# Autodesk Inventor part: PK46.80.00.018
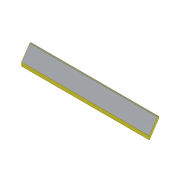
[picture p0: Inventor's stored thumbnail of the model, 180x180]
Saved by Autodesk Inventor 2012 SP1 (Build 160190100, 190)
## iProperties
Shininess: 64.0
Length Units: 11269
Angle Units: 11279
Time Units: 11290
Mass Units: 11283
Length Display Precision: 3
Angle Display Precision: 2
Compacted: True
Part Number: PK46.80.00.018
Document SubType Name: Modeling
Created: 2005-01
Material: Steel, Mild
Designer: SAlex
Manufacturer: Standard
Standards Organization: Custom
Density: 7.86 g/cm^3
Density: 0.0
Volumn: 0.0
Area: 0.0
PropertySet Name: Model Information
Control State: 0
Master: False
Checked Out: False
Checked Out Date: 2008-10-15
Last Check In Date: 2008-10-15
Author: SAlex
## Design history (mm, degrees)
sketch "Sketch1"
  geometry: L1 (0, 0)-(677, 0); L2 (677, 0)-(752, -125); L3 (752, -125)-(75, -125); L4 (75, -125)-(0, 0)
  constraints: 8 end point, 2 parallel, 1 horizontal, 1 other
  dimensions: "d0" = 677 distance of L1.start L1.end; "d1" = 125 distance between parallel lines of L3 L1; "d2" = 75 horizontal distance of L3.end L1.start
extrude "Extrusion1" new body sketch "Sketch1" distance "d3" = 19; taper "d4" = 0 deg
chamfer "Chamfer1" distance "d5" = 10; stored, may be unused: angle "d6" = 60 deg, second distance "d7" = 10
body "Solid1"
